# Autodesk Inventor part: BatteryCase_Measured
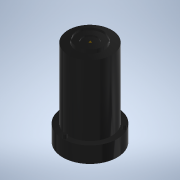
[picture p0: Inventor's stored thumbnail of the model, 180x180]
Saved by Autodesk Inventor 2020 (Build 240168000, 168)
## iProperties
Created: 2020-09
Part Number: BatteryCase_Measured
Material: Acetal Resin, Black
Document SubType Name: Modeling
Designer: biggshj
Manufacturer: Standard
Standards Organization: Custom
Density: 1.72439 g/cm^3
Appearance: Smooth - Black
Mass: 10470 g
Surface Area: 2156.45 cm^2
Volume: 6071.72 cm^3
Company: NIWA Instrument Systems
Author: biggshj
Revision Number: 1
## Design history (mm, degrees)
sketch "Sketch1"
  geometry: C1 r 76 at (0, 0); 1 further point
  constraints: 1 centre point, 1 coincident
  dimensions: "d0" = 152 diameter of C1
extrude "Extrusion1" new body sketch "Sketch1" distance "d1" = 245; taper "d2" = 0 deg
sketch "Sketch2"
  geometry: C1 r 95 at (0, 0); 1 further point
  constraints: 1 centre point, 1 coincident
  dimensions: "d3" = 190 diameter of C1
extrude "Extrusion2" join sketch "Sketch2" distance "d4" = 56; taper "d5" = 0 deg
workpoint "Work Point1"
sketch "Sketch3"
  geometry: L1 (76, 245)-(-76, 245) reference; L2 (25.5, 245)-(48.5, 245); L3 (48.5, 258)-(45.5, 258); L4 (45.5, 258)-(45.5, 250); L5 (45.5, 250)-(25.5, 250); L6 (25.5, 250)-(25.5, 245); L7 (48.5, 245)-(48.5, 258); L8 (25.5, 245)-(0, 245); L9 (0, -118.8)-(0, 320.8) reference; 1 further point
  constraints: 14 end point, 3 perpendicular, 2 point on line, 1 horizontal, 1 midpoint, 1 vertical
  dimensions: "d6" = 25.5 distance of L8.end L2.start; "d7" = 5 distance of L5.end L2.start; "d8" = 3 distance of L3.start L3.end; "d9" = 23 distance of L2.start L2.end; "d10" = 8 distance of L3.end L4.end
revolve "Revolution1" sketch "Sketch3" stored, may be unused: angle "d11" = 90 deg
sketch "Sketch4"
  geometry: C1 r 6 at (0, -88); 1 further point
  constraints: 1 centre point
  dimensions: "d12" = 12 diameter of C1; "d13" = 88 distance of point (0, 0) C1.centre
extrude "Extrusion3" join sketch "Sketch4" distance "d14" = 13; taper "d15" = 0 deg
pattern_circular "Circular Pattern1" dims angle "d17" = 360 deg
body "Solid1"
